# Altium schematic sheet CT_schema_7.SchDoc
size 274 x 160 mm
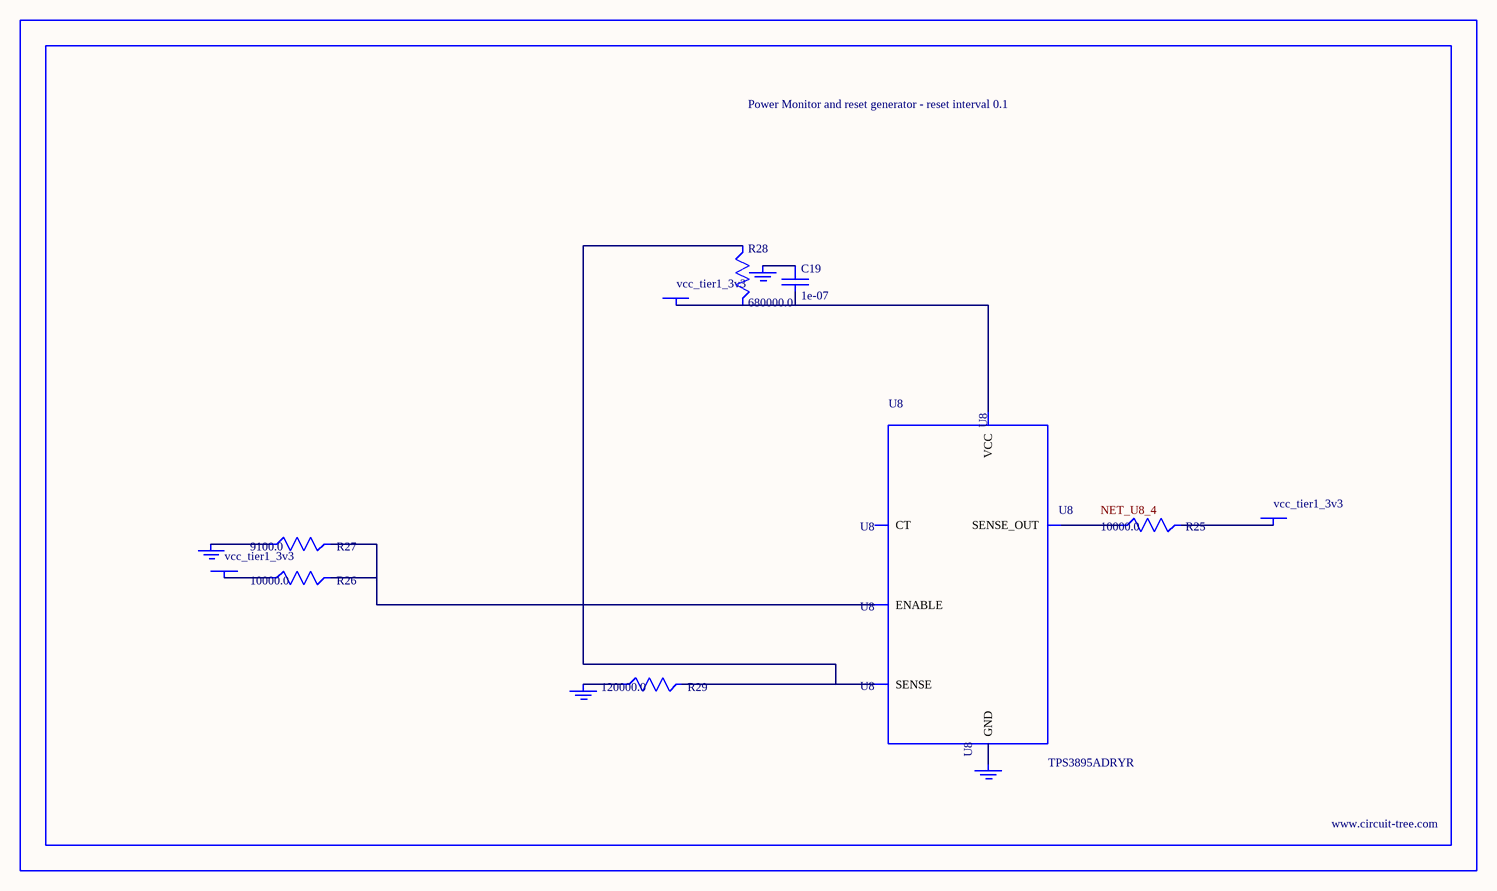
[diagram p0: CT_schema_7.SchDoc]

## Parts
BORDER6  (no value)
C19  1e-07  [C0402]
GND_INSTANCE_6_0  (no value)
GND_INSTANCE_6_1  (no value)
GND_INSTANCE_6_2  (no value)
GND_INSTANCE_6_3  (no value)
POWER_INSTANCE_6_0  vcc_tier1_3v3
POWER_INSTANCE_6_1  vcc_tier1_3v3
POWER_INSTANCE_6_2  vcc_tier1_3v3
R25  10000.0  [R0603]
R26  10000.0  [R0603]
R27  9100.0  [R0603]
R28  680000.0  [R0603]
R29  120000.0  [R0603]
U8  TPS3895ADRYR  [SON-6]

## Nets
NetC19_1: C19.1 GND_INSTANCE_6_2.0(GND)
NetC19_2: C19.2 POWER_INSTANCE_6_2.0(PWR) R28.2 U8.6(VCC)
NetGND_INSTANCE_6_0_0: GND_INSTANCE_6_0.0(GND) R27.1
NetGND_INSTANCE_6_1_0: GND_INSTANCE_6_1.0(GND) R29.1
NetGND_INSTANCE_6_3_0: GND_INSTANCE_6_3.0(GND) U8.2(GND)
NetPOWER_INSTANCE_6_0_0: POWER_INSTANCE_6_0.0(PWR) R26.1
NetPOWER_INSTANCE_6_1_0: POWER_INSTANCE_6_1.0(PWR) R25.2
NetR25_1: R25.1 U8.4(SENSE_OUT)
NetR26_2: R26.2 R27.2 U8.1(ENABLE)
NetR28_1: R28.1 R29.2 U8.3(SENSE)

Not connected (* = marked no-connect by the designer): U8 5(CT)

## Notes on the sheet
- Labels drawn without touching a wire or pin: NET_U8_4

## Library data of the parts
BORDER6 = BORDER_PAGE6
C19 = C0402C104K3RACTU
GND_INSTANCE_6_0-GND_INSTANCE_6_3 = GND
POWER_INSTANCE_6_0-POWER_INSTANCE_6_2 = PWR
R25 R26 = RC0603JR-0710KL
R27 = RC0603JR-079K1L
R28 = RC0603JR-07680KL
R29 = RC0603JR-07120KL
